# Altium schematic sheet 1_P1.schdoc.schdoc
size 309 x 223 mm; Symbol: Sheet-Symbol_A4; Device: Sheet-Symbol_A4; @Page Name: P1; @Create Date: 2024-03-08; @Page Count: 1; @Page No: 1; @Project Name: minifoc_test_4.0; @Schematic Name: schematic1_1; @Update Date: 2024-03-08; Company: 嘉立创EDA; Drawed: hlchen2021; Page Size: A4; Reviewed: hlchen2021; Version: V1.0
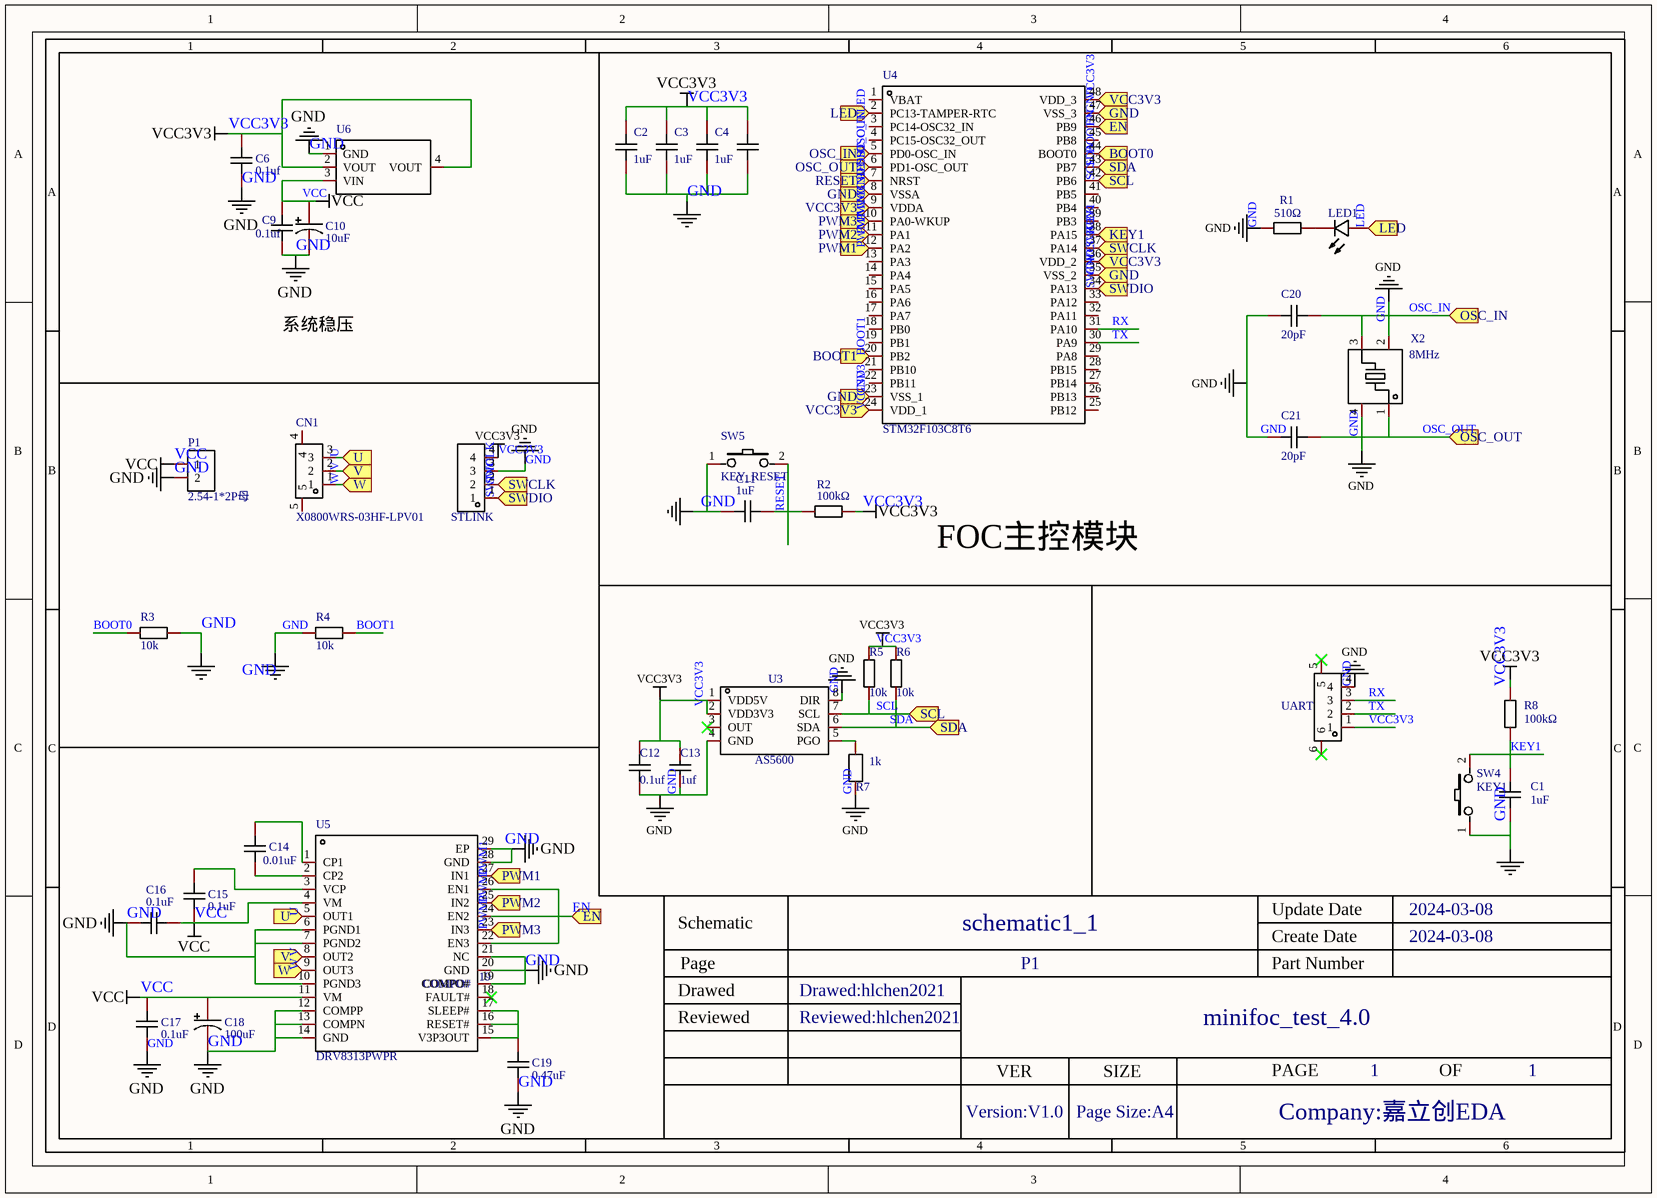
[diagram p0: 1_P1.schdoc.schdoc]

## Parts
C1  1uF  [C0603]
C2  1uF  [C0603]
C3  1uF  [C0603]
C4  1uF  [C0603]
C5  1uF  [C0603]  (value not drawn)
C6  0.1uf  [C0603]
C9  0.1uf  [C0603]
C10  10uF  [CAP-SMD_L3.2-W1.6-RD]
C11  1uF  [C0603]
C12  0.1uf  [C0603]
C13  1uf  [C0603]
C14  0.01uF  [C0603]
C15  0.1uF  [C0603]
C16  0.1uF  [C0603]
C17  0.1uF  [C0603]
C18  100uF  [CAP-SMD_L6.0-W3.2-R-RD]
C19  0.47uF  [C0603]
C20  20pF  [C0603]
C21  20pF  [C0603]
CN1  X0800WRS-03HF-LPV01  [CONN-SMD_X0800WRS-03HF-LPV01]
LED1  FC-DA1608HRK-620D  [LED0603-FD]  (value not drawn)
P1  2.54-1*2P母  [HDR-TH_2P-P2.54-V-F]
R1  510Ω  [R0603]
R2  100kΩ  [R0603]
R3  10k  [R0603]
R4  10k  [R0603]
R5  10k  [R0603]
R6  10k  [R0603]
R7  1k  [R0603]
R8  100kΩ  [R0603]
STLINK  2.54-1*4P反弯排针  [HDR-TH_4P-P2.54-H-M-W10.4]  (value not drawn)
SW4  KEY1  [SW-SMD_L4.0-W2.9-LS5.0]
SW5  KEY_RESET  [SW-SMD_L4.0-W2.9-LS5.0]
U3  AS5600  [SOIC-8_L5.0-W4.0-P1.27-LS6.0-BL]
U4  STM32F103C8T6  [LQFP-48_L7.0-W7.0-P0.50-LS9.0-BL]
U5  NAME: COMPO#  NUMBER: 19  [HTSSOP-28_L9.8-W4.5-P0.65-LS6.6-BL-EP]  (hidden comment: DRV8313PWPR)
U6  AMS1117-3.3_C6186  [SOT-223-3_L6.5-W3.4-P2.30-LS7.0-BR]  (value not drawn)
UART  HDGC1002WR-S-4P  [CONN-SMD_4P-P1.00_HDGC_HDGC1002WR-S-4P]  (value not drawn)
X2  8MHz  [OSC-SMD_4P-L3.2-W2.5-BL]

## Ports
BOOT0 (in), BOOT1 (in), EN (in), GND (in), KEY1 (in), LED (in), OSC_IN (in), OSC_OUT (in), PWM1 (in), PWM2 (in), PWM3 (in), RESET (in), SCL (in), SDA (in), SWCLK (in), SWDIO (in), U (in), V (in), VCC3V3 (in), W (in)

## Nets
GND: C1.1 C2.1 C3.1 C4.1 C5.1 C6.1 C9.1 C10.2 C11.1 C12.1 C13.1 C16.2 C17.1 C18.2 C19.2 C20.1 C21.1 C21.2 P1.2 R1.1 R3.2 R4.1 R7.1 STLINK.3 SW4.1 SW5.1 U3.4(GND) U3.8(DIR) U4.6(PD1-OSC_OUT) U4.8(VSSA) U4.23(VSS_1) U4.35(VSS_2) U4.47(VSS_3) U5.6(PGND1) U5.7(PGND2) U5.10(PGND3) U5.12(COMPP) U5.13(COMPN) U5.14(GND) U5.19(COMPO#) U5.20(GND) U5.21(NC) U5.28(GND) U5.29(EP) U6.1(GND) UART.4 X2.1 X2.2(GND) X2.4(GND) ; port OSC_OUT, port GND  [also labelled OSC_OUT]
VCC: C9.2 C10.1 C15.1 C16.1 C17.2 C18.1 P1.1 U5.4(VM) U5.11(VM) U6.3(VIN)
VCC3V3: C2.2 C3.2 C4.2 C5.2 C6.2 C12.2 C13.2 R2.2 R5.2 R6.2 R8.2 STLINK.4 U3.1(VDD5V) U3.2(VDD3V3) U4.9(VDDA) U4.24(VDD_1) U4.36(VDD_2) U4.48(VDD_3) U6.2(VOUT) U6.4(VOUT) UART.1 ; port VCC3V3
BOOT0: R3.1 U4.44(BOOT0) ; port BOOT0
BOOT1: R4.2 U4.20(PB2) ; port BOOT1
EN: U4.46(PB9) U5.22(EN3) U5.24(EN2) U5.26(EN1) ; port EN
KEY1: C1.2 R8.1 SW4.2 U4.38(PA15) ; port KEY1
LED: LED1.1(A) U4.2(PC13-TAMPER-RTC) ; port LED
OSC_IN: C20.2 U4.5(PD0-OSC_IN) X2.3 ; port OSC_IN
PWM1: U4.12(PA2) U5.27(IN1) ; port PWM1
PWM2: U4.11(PA1) U5.25(IN2) ; port PWM2
PWM3: U4.10(PA0-WKUP) U5.23(IN3) ; port PWM3
RESET: C11.2 R2.1 SW5.2 U4.7(NRST) ; port RESET
RX: U4.31(PA10) UART.3
SCL: R5.1 U3.7(SCL) U4.42(PB6) ; port SCL
SDA: R6.1 U3.6(SDA) U4.43(PB7) ; port SDA
SWCLK: STLINK.2 U4.37(PA14) ; port SWCLK
SWDIO: STLINK.1 U4.34(PA13) ; port SWDIO
TX: U4.30(PA9) UART.2
U: CN1.3 U5.5(OUT1) ; port U
V: CN1.2 U5.8(OUT2) ; port V
W: CN1.1 U5.9(OUT3) ; port W
NetC14_1: C14.1 U5.2(CP2)
NetC14_2: C14.2 U5.1(CP1)
NetC15_2: C15.2 U5.3(VCP)
NetC19_1: C19.1 U5.15(V3P3OUT) U5.16(RESET#) U5.17(SLEEP#)
NetLED1_2: LED1.2(K) R1.2
NetR7_2: R7.2 U3.5(PGO)

Not connected (* = marked no-connect by the designer): CN1 4 5; U3 3(OUT)*; U4 1(VBAT) 3(PC14-OSC32_IN) 4(PC15-OSC32_OUT) 13(PA3) 14(PA4) 15(PA5) 16(PA6) 17(PA7) 18(PB0) 19(PB1) 21(PB10) 22(PB11) 25(PB12) 26(PB13) 27(PB14) 28(PB15) 29(PA8) 32(PA11) 33(PA12) 39(PB3) 40(PB4) 41(PB5) 45(PB8); U5 18(FAULT#)*; UART 5* 6*

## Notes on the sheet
- 系统稳压
- FOC主控模块
- Labels drawn without touching a wire or pin: GND

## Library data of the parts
C1-C5 C11 C13 = 0603F105M160NT: 容值:1uF;精度:±20%;额定电压:16V;材质(温度系数):Y5V;; Manufacturer: FH(风华); Add into BOM: yes; Tolerance: ±20%; Voltage Rated: 16V; Temperature Coefficient: Y5V
C6 C9 = 0.1uf: Convert to PCB: yes
C10 = TC212A106M010A: Manufacturer: Sunlord; Convert to PCB: yes
C12 = CC0603KRX7R9BB104: 容值:100nF;精度:±10%;额定电压:50V;材质(温度系数):X7R;; Manufacturer: YAGEO(国巨); Add into BOM: yes; Value: 100nF; Tolerance: ±10%; Voltage Rated: 50V; Temperature Coefficient: X7R
C14 = 0.01uF: Convert to PCB: yes; NAME: 2
C15 = 0.1uF: Convert to PCB: yes; NAME: 2
C16 C17 = 0.1uF: Convert to PCB: yes; NUMBER: 2
C18 = CA45-C-10V-100μF-K: Manufacturer: TORCH; Convert to PCB: yes
C19 = 0.47uF: Convert to PCB: yes; NUMBER: 1
C20 C21 = 0603CG200J101NT: 容值:20pF;精度:±5%;额定电压:100V;材质(温度系数):C0G;额定电压(VAC):-;; Manufacturer: FH(风华); Add into BOM: yes; Tolerance: ±5%; Voltage Rated: 100V; Temperature Coefficient: C0G
CN1 = X0800WRS-03HF-LPV01: 插针结构:1x3P;间距:0.8mm;安装方式:卧贴;行距:-;总PIN数:3P;排数:1;每排PIN数:3;参考系列:-;额定电流:500mA;触头材质:磷青铜;触头镀层:金;工作温度范围:-25℃~+85℃;; Manufacturer: XKB Connectivity(中国星坤); Add into BOM: yes; Pins Structure: 1x3P; Pitch: 0.8mm; Number of PINs Per Row: 3; Current Rating (Max): 500mA
LED1 = FC-DA1608HRK-620D: Manufacturer: NATIONSTAR; Convert to PCB: yes
P1 = 2.54-1*2P母: 排数:单排;总孔位数:2P;间距:2.54mm;插孔结构:1x2P;行距:-;安装类型:直插;塑高:-;触头材质:-;触头镀层:-;; Manufacturer: BOOMELE(博穆精密); Symbol: Header-Female-2.54_1x2; Add into BOM: yes; Number of Holes: 2P; Pitch: 2.54mm; Holes Structure: 1x2P
R1 = RS-03K511JT: Manufacturer: FH; Resistance: 510; Convert to PCB: yes
R2 R8 = HoLTT0603-1/10W-100KR-1%: 阻值:100kΩ;功率:100mW;; Manufacturer: Milliohm(毫欧); Symbol: 100k; Add into BOM: yes; Power(Watts): 100mW
R3-R6 = 0603WAF1002T5E: 电阻类型:厚膜电阻;阻值:10kΩ;精度:±1%;功率:100mW;温度系数:±100ppm/;最大工作电压:75V;工作温度范围:-55~+155;; Manufacturer: UNI-ROYAL(厚声); Add into BOM: yes; Value: 10kΩ; Tolerance: ±1%; Power(Watts): 100mW; Overload Voltage (Max): 75V
R7 = SCR0603J1K: Manufacturer: VO(翔胜); Add into BOM: yes
STLINK = 2.54-1*4P反弯排针: 间距:2.54mm;总PIN位数:4;排数:1;插针结构:1x4P;行距:-;安装类型:弯插;圆针/方针:方针;额定电流:3A;额定电压:-;配合针长度:6mm;塑高:-;端接针长度:-;触头材质:-;触头镀层:-;工作温度范围:-55~+105;颜色:黑色;; Manufacturer: BOOMELE(博穆精密); Add into BOM: yes; Pitch: 2.54mm; Pin Structure: 1x4P; Circluar Pins/Square Pins: 方针; Current Rating (Max): 3A
SW4 SW5 = KEY-3*4*2: Add into BOM: yes
U3 = AS5600-ASOM: 非接触12bit磁角度位置传感器; Manufacturer: ams(艾迈斯半导体); Add into BOM: yes
U4 = STM32F103C8T6: CPU内核:ARM Cortex-M3;CPU最大主频:72MHz;工作电压范围:2V~3.6V;内部振荡器:有;程序 FLASH容量:64K@x8bit;RAM总容量:20KB;EEPROM/数据 FLASH容量:-;GPIO端口数量:37;ADC(单元数/通道数/位数):1@x10ch/12bit;外设/功能/协议栈:温度传感器；DMA；看门狗；POR；PWM;工作温度范围:-40~+85;; Manufacturer: ST(意法半导体); Add into BOM: yes; Maximum Frequency: 72MHz; Internal Oscillator: 有; RAM Size: 20KB; GPIO Ports Number: 37
U5 = DRV8313PWPR: DRV8313 三路 1/2 H 桥驱动器 IC; Manufacturer: TI(德州仪器); Add into BOM: yes
U6 = AMS1117-3.3_C6186: 输出类型:固定;输出极性:正;输出通道数:1;最大输入电压:-;输出电压:3.3V;压差:1.3V@(800mA);静态电流(地电流):-;输出电流:1A;电源纹波抑制比(PSRR):72dB@(120Hz);噪声:-;特性:-;工作温度:-;; Manufacturer: 美国AMS; Add into BOM: yes; Output Type: 固定; Output Polarity: 正; Number of Outputs: 1; Output Voltage: 3.3V; Output Current: 1A
UART = HDGC1002WR-S-4P: 参考系列:-;间距:1mm;插针结构:1x4P;排数:1;每排PIN数:4;行距:-;公母:公型插针;安装方式:卧贴;额定电流:1A;工作温度范围:-25~+70;; Manufacturer: HDGC(华德共创); Add into BOM: yes; Pitch: 1mm; Pins Structure: 1x4P; Number of PINs Per Row: 4; Gender: 公型插针; Current Rating (Max): 1A
X2 = 3225-8.00-10-10-10/A: 晶振类型:贴片无源晶振;频率:8MHz;频率公差:±10ppm;频率稳定度:-;负载电容:10pF;工作温度:-;; Manufacturer: LIMING(利明); Add into BOM: yes; Crystal Type: 贴片无源晶振; Frequency Tolerance: ±10ppm; Load Capacitance: 10pF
